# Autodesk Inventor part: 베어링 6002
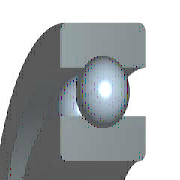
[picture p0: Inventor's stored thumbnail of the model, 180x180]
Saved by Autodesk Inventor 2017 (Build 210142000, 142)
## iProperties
Created: 2012-02
Part Number: 베어링 6002
Material: 강철, 연강
Description: 깊은 그루브 볼 베어링
Document SubType Name: Modeling
Standard: KS B 2023
Designer: mduedu
Standards Organization: KS
Language: ko-KR
Size Designation: 6002 - 15 x 32 x 9
Categories: <MemberInstance><Categories><Category DisplayName="샤프트 부품" InternalName="7f7aeb1f-a693-4053-b835-cee3144e0d98" Mnemonic="SHFT"><Category DisplayName="베어링" Inter
Density: 7.86 g/cm^3
Mass: 29.8124 g
Surface Area: 39.9079 cm^2
Volume: 3.79292 cm^3
Appearance: 분홍색
IsCustomPart: 1
Author: mduedu
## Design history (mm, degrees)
sketch "스케치" dims "d0" = 4.42 (= -0.26 x WD + 0.26 x BD)
  geometry: L1 (2.29, 11.75)-(6.71, 11.75); L2 (4.5, 11.75)-(4.5, 9.54); L3 (4.5, 11.75)-(4.5, 13.96); L4 (2.858, 10.271)-(0, 10.271); L5 (0, 7.5)-(9, 7.5); L6 (2.858, 13.229)-(0, 13.229); L7 (0, 16)-(9, 16); L8 (9, 7.5)-(9, 10.271); L9 (6.142, 10.271)-(9, 10.271); L10 (6.142, 13.229)-(9, 13.229); L11 (9, 16)-(9, 13.229); L12 (-1.4, 0)-(8.4, 0) reference; L13 (0, -0.3)-(0, 5.3) reference
  constraints: 22 end point, 4 point on line, 2 collinear, 2 perpendicular, 2 symmetric about line, 1 midpoint, 1 parallel, 14 other
  dimensions: "d9" = 15 diameter of L5 L12 (= WD); "d11" = 32 diameter of L7 L12 (= BD); "d12" = 9 distance between parallel lines of L8 L13 (= KB); "d13" = 20.542 diameter of L9 L12 (= 0.326 x BD + 0.674 x WD)
revolve "본체" stored, may be unused: angle "d6" = 90 deg
revolve "볼" stored, may be unused: angle "d7" = 90 deg
pattern_circular "IDS_ARRAYBALL[SIMPL:T]" dims angle "d3" = 360 deg
body "Solid1"
fillet "모깎기1" dims "d1" = 0.3 (= KRS)
other parameters: "WD" = 15 [user parameter; used in 5 equation terms], "BD" = 32 [user parameter; used in 5 equation terms], "KB" = 9 [user parameter; used in 1 equation term], "KRS" = 0.3 [user parameter; used in 1 equation term], "d4" = 0, "d5" = 0, "d8" = 0, "d14" = 0, "d15" = 0, "BBA" = 0 [user parameter], "BC0" = 2850000 [user parameter], "BC" = 5590000 [user parameter], "BR" = 16 (= 0.5 x BD) [user parameter], "WR" = 7.5 (= 0.5 x WD) [user parameter]
